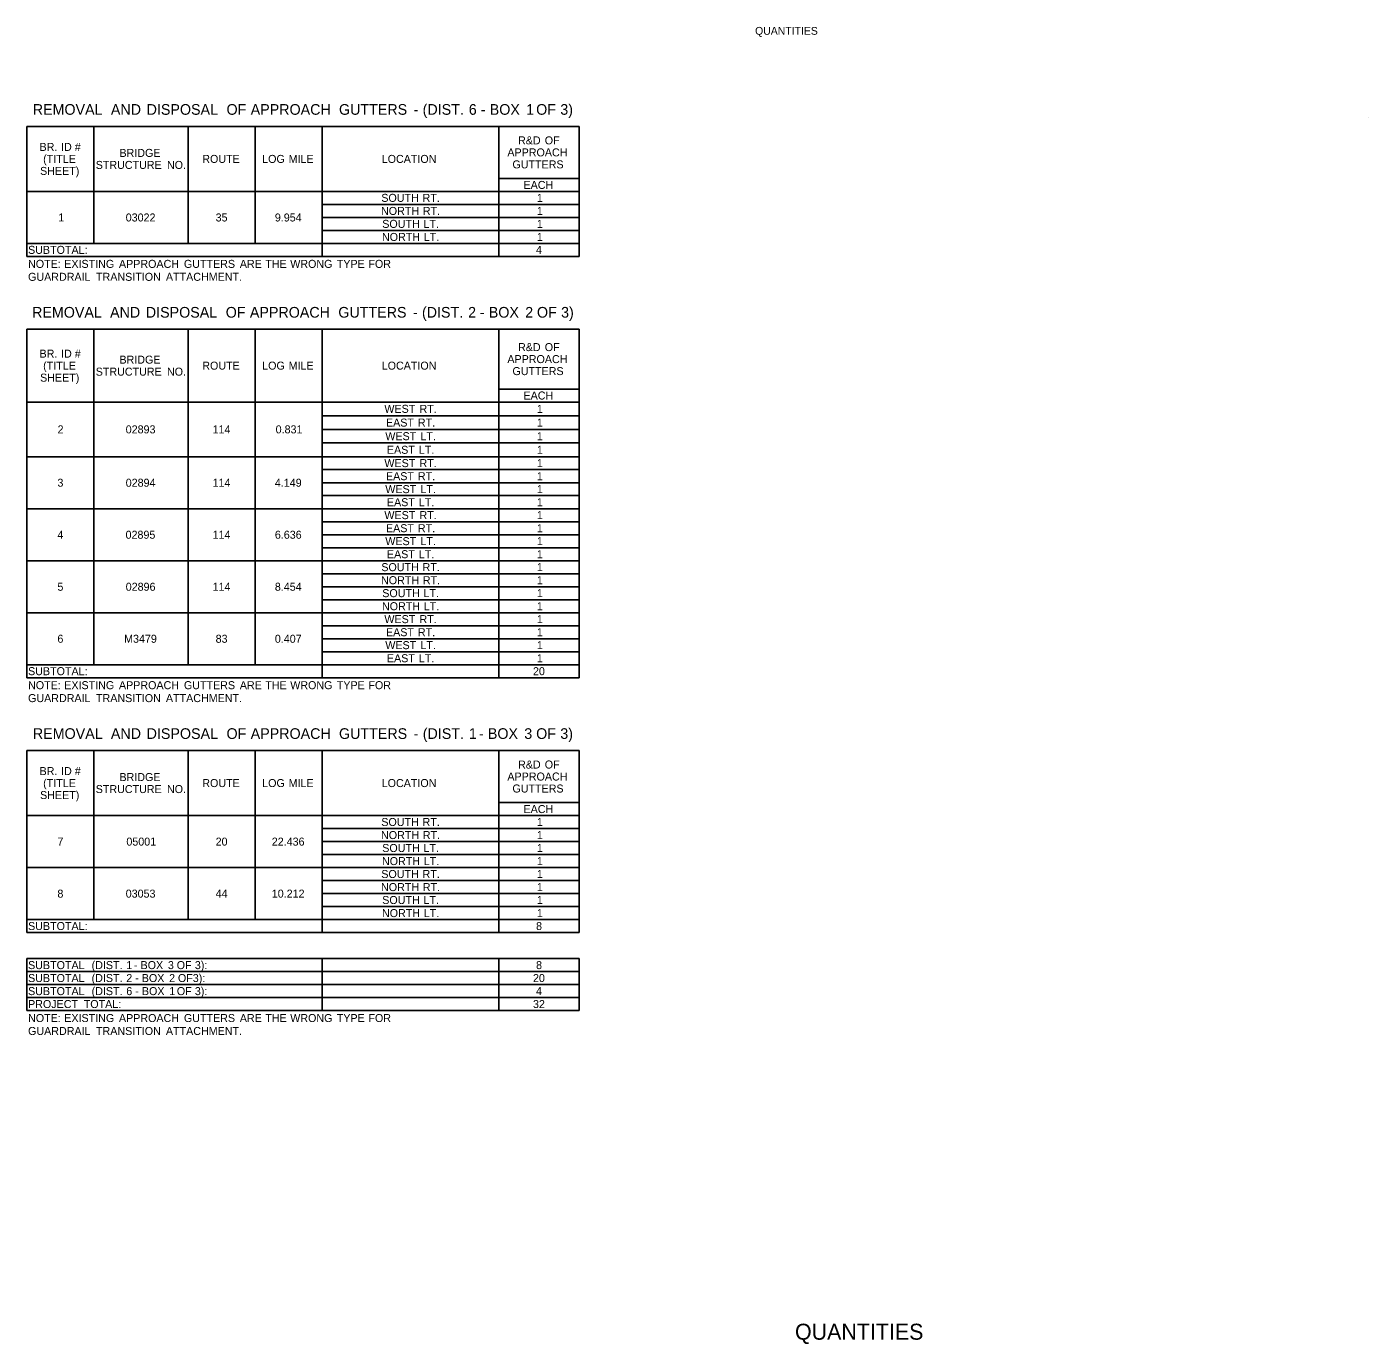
# Model space of a CAD drawing. Extents: x 542596 to 1930787, y -1948294 to 596640.
# Drawn here: x 560317 to 561323, y -1947044 to -1946056 of the extents above; entities that cross this region are included whole.
import ezdxf

# ---------------------------------------------------------------- set-up
doc = ezdxf.new("R2010")
doc.units = 0
for name, color, linetype in [('Default', 7, 'Continuous'), ('R_Border', 7, 'Continuous'), ('R_Border Prem', 7, 'Continuous')]:
    doc.layers.add(name, color=color, linetype=linetype)

msp = doc.modelspace()

# ---------------------------------------------------------------- linework, layer by layer
at = {"layer": 'Default'}
for p, q in [((560317.3, -1946131.1), (560731.2, -1946131.1)), ((560317.3, -1946228.6), (560317.3, -1946131.1)), ((560317.3, -1946228.6), (560317.3, -1946131.1)), ((560367.5, -1946218.9), (560367.5, -1946131.1)), ((560438.2, -1946218.9), (560438.2, -1946131.1)), ((560488.4, -1946218.9), (560488.4, -1946131.1)), ((560538.6, -1946228.6), (560538.6, -1946131.1)), ((560671.2, -1946228.6), (560671.2, -1946131.1)), ((560731.2, -1946228.6), (560731.2, -1946131.1)), ((561322.8, -1946124.4), (561322.8, -1946124.4)), ((560671.2, -1946170.1), (560731.2, -1946170.1)), ((560671.2, -1946170.1), (560731.2, -1946170.1)), ((560317.3, -1946179.9), (560731.2, -1946179.9)), ((560438.2, -1946179.9), (560538.6, -1946179.9)), ((560538.6, -1946189.6), (560731.2, -1946189.6)), ((560538.6, -1946199.4), (560731.2, -1946199.4)), ((560538.6, -1946209.1), (560731.2, -1946209.1)), ((560317.3, -1946218.9), (560731.2, -1946218.9)), ((560538.6, -1946228.6), (560538.6, -1946218.9)), ((560671.2, -1946218.9), (560731.2, -1946218.9)), ((560317.3, -1946228.6), (560731.2, -1946228.6)), ((560317.3, -1946283.2), (560731.2, -1946283.2)), ((560317.3, -1946544.5), (560317.3, -1946283.2)), ((560317.3, -1946544.5), (560317.3, -1946283.2)), ((560367.5, -1946534.8), (560367.5, -1946283.2)), ((560438.2, -1946534.8), (560438.2, -1946283.2)), ((560488.4, -1946534.8), (560488.4, -1946283.2)), ((560538.6, -1946544.5), (560538.6, -1946283.2)), ((560671.2, -1946544.5), (560671.2, -1946283.2)), ((560731.2, -1946544.5), (560731.2, -1946283.2)), ((560671.2, -1946328.1), (560731.2, -1946328.1)), ((560671.2, -1946328.1), (560731.2, -1946328.1)), ((560317.3, -1946337.8), (560731.2, -1946337.8)), ((560671.2, -1946337.8), (560731.2, -1946337.8)), ((560538.6, -1946348.1), (560731.2, -1946348.1)), ((560538.6, -1946358.3), (560731.2, -1946358.3)), ((560538.6, -1946368.5), (560731.2, -1946368.5)), ((560317.3, -1946378.8), (560671.2, -1946378.8)), ((560538.6, -1946378.8), (560671.2, -1946378.8)), ((560671.2, -1946378.8), (560731.2, -1946378.8)), ((560671.2, -1946378.8), (560731.2, -1946378.8)), ((560538.6, -1946388.5), (560731.2, -1946388.5)), ((560538.6, -1946398.3), (560731.2, -1946398.3)), ((560538.6, -1946408), (560731.2, -1946408)), ((560317.3, -1946417.8), (560731.2, -1946417.8)), ((560538.6, -1946417.8), (560671.2, -1946417.8)), ((560671.2, -1946417.8), (560731.2, -1946417.8)), ((560538.6, -1946427.5), (560731.2, -1946427.5)), ((560538.6, -1946437.3), (560731.2, -1946437.3)), ((560538.6, -1946447), (560731.2, -1946447)), ((560317.3, -1946456.8), (560731.2, -1946456.8)), ((560538.6, -1946456.8), (560671.2, -1946456.8)), ((560671.2, -1946456.8), (560731.2, -1946456.8)), ((560538.6, -1946466.5), (560731.2, -1946466.5)), ((560538.6, -1946476.3), (560731.2, -1946476.3)), ((560538.6, -1946486), (560731.2, -1946486)), ((560317.3, -1946495.8), (560731.2, -1946495.8)), ((560317.3, -1946495.8), (560538.6, -1946495.8)), ((560538.6, -1946505.5), (560731.2, -1946505.5)), ((560538.6, -1946515.3), (560731.2, -1946515.3)), ((560538.6, -1946525), (560731.2, -1946525)), ((560317.3, -1946534.8), (560731.2, -1946534.8)), ((560538.6, -1946534.8), (560671.2, -1946534.8)), ((560538.6, -1946544.5), (560538.6, -1946534.8)), ((560671.2, -1946534.8), (560731.2, -1946534.8)), ((560317.3, -1946544.5), (560731.2, -1946544.5)), ((560317.3, -1946599.1), (560731.2, -1946599.1)), ((560317.3, -1946735.6), (560317.3, -1946599.1)), ((560317.3, -1946735.6), (560317.3, -1946599.1)), ((560367.5, -1946725.9), (560367.5, -1946599.1)), ((560438.2, -1946725.9), (560438.2, -1946599.1)), ((560488.4, -1946725.9), (560488.4, -1946599.1)), ((560538.6, -1946735.6), (560538.6, -1946599.1)), ((560671.2, -1946735.6), (560671.2, -1946599.1)), ((560731.2, -1946735.6), (560731.2, -1946599.1)), ((560671.2, -1946638.1), (560731.2, -1946638.1)), ((560671.2, -1946638.1), (560731.2, -1946638.1)), ((560317.3, -1946647.9), (560731.2, -1946647.9)), ((560538.6, -1946657.6), (560731.2, -1946657.6)), ((560538.6, -1946667.4), (560731.2, -1946667.4)), ((560538.6, -1946677.1), (560731.2, -1946677.1)), ((560317.3, -1946686.9), (560731.2, -1946686.9)), ((560438.2, -1946686.9), (560538.6, -1946686.9)), ((560538.6, -1946696.6), (560731.2, -1946696.6)), ((560538.6, -1946706.4), (560731.2, -1946706.4)), ((560538.6, -1946716.1), (560731.2, -1946716.1)), ((560317.3, -1946725.9), (560731.2, -1946725.9)), ((560538.6, -1946735.6), (560538.6, -1946725.9)), ((560317.3, -1946735.6), (560731.2, -1946735.6)), ((560317.3, -1946755.1), (560731.2, -1946755.1)), ((560317.3, -1946755.1), (560731.2, -1946755.1)), ((560317.3, -1946794.1), (560317.3, -1946755.1)), ((560317.3, -1946794.1), (560317.3, -1946755.1)), ((560538.6, -1946784.4), (560538.6, -1946755.1)), ((560538.6, -1946794.1), (560538.6, -1946755.1)), ((560671.2, -1946794.1), (560671.2, -1946755.1)), ((560731.2, -1946794.1), (560731.2, -1946755.1)), ((560317.3, -1946764.9), (560731.2, -1946764.9)), ((560317.3, -1946774.6), (560731.2, -1946774.6)), ((560317.3, -1946784.4), (560731.2, -1946784.4)), ((560317.3, -1946794.1), (560731.2, -1946794.1))]:
    msp.add_line(p, q, dxfattribs=at)

# ---------------------------------------------------------------- texts
for s, height, p in [('REMOVAL', 8, (560321.7, -1946122.4)), (' AND', 8, (560377.3, -1946122.4)), (' DISPOSAL', 8, (560404.1, -1946122.4)), (' OF', 8, (560464, -1946122.4)), (' APPROACH', 8, (560482.1, -1946122.4)), (' GUTTERS', 8, (560548.3, -1946122.4)), (' -', 8, (560604.3, -1946122.4)), (' (DIST.', 8, (560611, -1946122.4)), (' 6', 8, (560645.6, -1946122.4)), (' -', 8, (560654.6, -1946122.4)), (' BOX', 8, (560661.3, -1946122.4)), (' 1', 8, (560688.6, -1946122.4)), (' OF', 8, (560696.1, -1946122.4)), (' 3)', 8, (560714.2, -1946122.4)), ('BR.', 6, (560326.8, -1946149.5)), (' ID', 6, (560340.7, -1946149.5)), (' #', 6, (560351, -1946149.5)), ('R&D', 6, (560685.5, -1946144.6)), (' OF', 6, (560703.3, -1946144.6)), ('(TITLE', 6, (560329.5, -1946158.5)), ('BRIDGE', 6, (560386.7, -1946154)), ('ROUTE', 6, (560448.8, -1946158.5)), ('LOG', 6, (560493.7, -1946158.5)), (' MILE', 6, (560511.3, -1946158.5)), ('LOCATION', 6, (560583.3, -1946158.5)), ('APPROACH', 6, (560677.5, -1946153.6)), ('SHEET)', 6, (560327.2, -1946167.5)), ('STRUCTURE', 6, (560368.9, -1946163)), (' NO.', 6, (560420.1, -1946163)), ('GUTTERS', 6, (560681.3, -1946162.6)), ('EACH', 6, (560689.6, -1946178)), ('SOUTH', 6, (560583, -1946187.7)), (' RT.', 6, (560611.7, -1946187.7)), ('1', 6, (560699.6, -1946187.7)), ('NORTH', 6, (560582.8, -1946197.5)), (' RT.', 6, (560611.9, -1946197.5)), ('1', 6, (560699.6, -1946197.5)), ('1', 6, (560340.8, -1946202.4)), ('03022', 6, (560391.4, -1946202.4)), ('35', 6, (560458.8, -1946202.4)), ('9.954', 6, (560503.2, -1946202.4)), ('SOUTH', 6, (560583.7, -1946207.2)), (' LT.', 6, (560612.4, -1946207.2)), ('1', 6, (560699.6, -1946207.2)), ('NORTH', 6, (560583.5, -1946217)), (' LT.', 6, (560612.6, -1946217)), ('1', 6, (560699.6, -1946217)), ('SUBTOTAL:', 6, (560318.2, -1946226.7)), ('4', 6, (560698.9, -1946226.7)), ('NOTE:', 6, (560318.2, -1946237.2)), (' EXISTING', 6, (560343.1, -1946237.2)), (' APPROACH', 6, (560384.1, -1946237.2)), (' GUTTERS', 6, (560432.8, -1946237.2)), (' ARE', 6, (560474.7, -1946237.2)), (' THE', 6, (560493.8, -1946237.2)), (' WRONG', 6, (560512.5, -1946237.2)), (' TYPE', 6, (560547.4, -1946237.2)), (' FOR', 6, (560571.1, -1946237.2)), ('GUARDRAIL', 6, (560318.2, -1946246.9)), (' TRANSITION', 6, (560366.9, -1946246.9)), (' ATTACHMENT.', 6, (560419.3, -1946246.9)), ('REMOVAL', 8, (560321.2, -1946274.5)), (' AND', 8, (560376.7, -1946274.5)), (' DISPOSAL', 8, (560403.5, -1946274.5)), (' OF', 8, (560463.4, -1946274.5)), (' APPROACH', 8, (560481.5, -1946274.5)), (' GUTTERS', 8, (560547.8, -1946274.5)), (' -', 8, (560603.7, -1946274.5)), (' (DIST.', 8, (560610.5, -1946274.5)), (' 2', 8, (560645.1, -1946274.5)), (' -', 8, (560653.9, -1946274.5)), (' BOX', 8, (560660.6, -1946274.5)), (' 2', 8, (560687.9, -1946274.5)), (' OF', 8, (560696.7, -1946274.5)), (' 3)', 8, (560714.8, -1946274.5)), ('R&D', 6, (560685.5, -1946299.6)), (' OF', 6, (560703.3, -1946299.6)), ('BR.', 6, (560326.8, -1946304.5)), (' ID', 6, (560340.7, -1946304.5)), (' #', 6, (560351, -1946304.5)), ('BRIDGE', 6, (560386.7, -1946309)), ('APPROACH', 6, (560677.5, -1946308.6)), ('(TITLE', 6, (560329.5, -1946313.5)), ('STRUCTURE', 6, (560368.9, -1946318)), (' NO.', 6, (560420.1, -1946318)), ('ROUTE', 6, (560448.8, -1946313.5)), ('LOG', 6, (560493.7, -1946313.5)), (' MILE', 6, (560511.3, -1946313.5)), ('LOCATION', 6, (560583.3, -1946313.5)), ('GUTTERS', 6, (560681.3, -1946317.6)), ('SHEET)', 6, (560327.2, -1946322.5)), ('EACH', 6, (560689.6, -1946335.9)), ('WEST', 6, (560585.3, -1946345.9)), (' RT.', 6, (560609.4, -1946345.9)), ('1', 6, (560699.6, -1946345.9)), ('EAST', 6, (560586.5, -1946356.2)), (' RT.', 6, (560608.2, -1946356.2)), ('1', 6, (560699.6, -1946356.2)), ('2', 6, (560340.3, -1946361.3)), ('02893', 6, (560391.4, -1946361.3)), ('114', 6, (560456.5, -1946361.3)), ('0.831', 6, (560503.8, -1946361.3)), ('WEST', 6, (560586, -1946366.4)), (' LT.', 6, (560610.1, -1946366.4)), ('1', 6, (560699.6, -1946366.4)), ('EAST', 6, (560587.2, -1946376.6)), (' LT.', 6, (560608.9, -1946376.6)), ('1', 6, (560699.6, -1946376.6)), ('WEST', 6, (560585.3, -1946386.6)), (' RT.', 6, (560609.4, -1946386.6)), ('1', 6, (560699.6, -1946386.6)), ('EAST', 6, (560586.5, -1946396.4)), (' RT.', 6, (560608.2, -1946396.4)), ('1', 6, (560699.6, -1946396.4)), ('3', 6, (560340.2, -1946401.3)), ('02894', 6, (560391.4, -1946401.3)), ('114', 6, (560456.5, -1946401.3)), ('4.149', 6, (560503.2, -1946401.3)), ('WEST', 6, (560586, -1946406.1)), (' LT.', 6, (560610.1, -1946406.1)), ('1', 6, (560699.6, -1946406.1)), ('EAST', 6, (560587.2, -1946415.9)), (' LT.', 6, (560608.9, -1946415.9)), ('1', 6, (560699.6, -1946415.9)), ('WEST', 6, (560585.3, -1946425.6)), (' RT.', 6, (560609.4, -1946425.6)), ('1', 6, (560699.6, -1946425.6)), ('4', 6, (560340.2, -1946440.3)), ('02895', 6, (560391.3, -1946440.3)), ('114', 6, (560456.5, -1946440.3)), ('6.636', 6, (560503.2, -1946440.3)), ('EAST', 6, (560586.5, -1946435.4)), (' RT.', 6, (560608.2, -1946435.4)), ('1', 6, (560699.6, -1946435.4)), ('WEST', 6, (560586, -1946445.1)), (' LT.', 6, (560610.1, -1946445.1)), ('1', 6, (560699.6, -1946445.1)), ('EAST', 6, (560587.2, -1946454.9)), (' LT.', 6, (560608.9, -1946454.9)), ('1', 6, (560699.6, -1946454.9)), ('SOUTH', 6, (560583, -1946464.6)), (' RT.', 6, (560611.7, -1946464.6)), ('1', 6, (560699.6, -1946464.6)), ('5', 6, (560340.2, -1946479.3)), ('02896', 6, (560391.4, -1946479.3)), ('114', 6, (560456.5, -1946479.3)), ('8.454', 6, (560503.2, -1946479.3)), ('NORTH', 6, (560582.8, -1946474.4)), (' RT.', 6, (560611.9, -1946474.4)), ('1', 6, (560699.6, -1946474.4)), ('SOUTH', 6, (560583.7, -1946484.1)), (' LT.', 6, (560612.4, -1946484.1)), ('1', 6, (560699.6, -1946484.1)), ('NORTH', 6, (560583.5, -1946493.9)), (' LT.', 6, (560612.6, -1946493.9)), ('1', 6, (560699.6, -1946493.9)), ('WEST', 6, (560585.3, -1946503.6)), (' RT.', 6, (560609.4, -1946503.6)), ('1', 6, (560699.6, -1946503.6)), ('6', 6, (560340.2, -1946518.3)), ('M3479', 6, (560390.2, -1946518.3)), ('83', 6, (560458.8, -1946518.3)), ('0.407', 6, (560503.2, -1946518.3)), ('EAST', 6, (560586.5, -1946513.4)), (' RT.', 6, (560608.2, -1946513.4)), ('1', 6, (560699.6, -1946513.4)), ('WEST', 6, (560586, -1946523.1)), (' LT.', 6, (560610.1, -1946523.1)), ('1', 6, (560699.6, -1946523.1)), ('EAST', 6, (560587.2, -1946532.9)), (' LT.', 6, (560608.9, -1946532.9)), ('1', 6, (560699.6, -1946532.9)), ('SUBTOTAL:', 6, (560318.2, -1946542.6)), ('20', 6, (560696.7, -1946542.6)), ('NOTE:', 6, (560318.2, -1946553.1)), (' EXISTING', 6, (560343.1, -1946553.1)), (' APPROACH', 6, (560384.1, -1946553.1)), (' GUTTERS', 6, (560432.8, -1946553.1)), (' ARE', 6, (560474.7, -1946553.1)), (' THE', 6, (560493.8, -1946553.1)), (' WRONG', 6, (560512.5, -1946553.1)), (' TYPE', 6, (560547.4, -1946553.1)), (' FOR', 6, (560571.1, -1946553.1)), ('GUARDRAIL', 6, (560318.2, -1946562.8)), (' TRANSITION', 6, (560366.9, -1946562.8)), (' ATTACHMENT.', 6, (560419.3, -1946562.8)), ('REMOVAL', 8, (560321.8, -1946590.4)), (' AND', 8, (560377.3, -1946590.4)), (' DISPOSAL', 8, (560404.1, -1946590.4)), (' OF', 8, (560464, -1946590.4)), (' APPROACH', 8, (560482.1, -1946590.4)), (' GUTTERS', 8, (560548.3, -1946590.4)), (' (DIST.', 8, (560611.1, -1946590.4)), (' 1', 8, (560645.7, -1946590.4)), (' BOX', 8, (560659.9, -1946590.4)), (' 3', 8, (560687.2, -1946590.4)), (' OF', 8, (560696.1, -1946590.4)), (' 3)', 8, (560714.2, -1946590.4)), (' -', 8, (560604.3, -1946590.4)), (' -', 8, (560653.2, -1946590.4)), ('BR.', 6, (560326.8, -1946617.5)), (' ID', 6, (560340.7, -1946617.5)), (' #', 6, (560351, -1946617.5)), ('BRIDGE', 6, (560386.7, -1946622)), ('APPROACH', 6, (560677.5, -1946621.6)), ('R&D', 6, (560685.5, -1946612.6)), (' OF', 6, (560703.3, -1946612.6)), ('(TITLE', 6, (560329.5, -1946626.5)), ('STRUCTURE', 6, (560368.9, -1946631)), (' NO.', 6, (560420.1, -1946631)), ('ROUTE', 6, (560448.8, -1946626.5)), ('LOG', 6, (560493.7, -1946626.5)), (' MILE', 6, (560511.3, -1946626.5)), ('LOCATION', 6, (560583.3, -1946626.5)), ('GUTTERS', 6, (560681.3, -1946630.6)), ('SHEET)', 6, (560327.2, -1946635.5)), ('EACH', 6, (560689.6, -1946646)), ('SOUTH', 6, (560583, -1946655.7)), (' RT.', 6, (560611.7, -1946655.7)), ('1', 6, (560699.6, -1946655.7)), ('7', 6, (560340.2, -1946670.4)), ('05001', 6, (560391.9, -1946670.4)), ('20', 6, (560458.8, -1946670.4)), ('22.436', 6, (560500.9, -1946670.4)), ('NORTH', 6, (560582.8, -1946665.5)), (' RT.', 6, (560611.9, -1946665.5)), ('1', 6, (560699.6, -1946665.5)), ('SOUTH', 6, (560583.7, -1946675.2)), (' LT.', 6, (560612.4, -1946675.2)), ('1', 6, (560699.6, -1946675.2)), ('NORTH', 6, (560583.5, -1946685)), (' LT.', 6, (560612.6, -1946685)), ('1', 6, (560699.6, -1946685)), ('SOUTH', 6, (560583, -1946694.7)), (' RT.', 6, (560611.7, -1946694.7)), ('1', 6, (560699.6, -1946694.7)), ('8', 6, (560340.2, -1946709.4)), ('03053', 6, (560391.4, -1946709.4)), ('44', 6, (560458.8, -1946709.4)), ('10.212', 6, (560500.9, -1946709.4)), ('NORTH', 6, (560582.8, -1946704.5)), (' RT.', 6, (560611.9, -1946704.5)), ('1', 6, (560699.6, -1946704.5)), ('SOUTH', 6, (560583.7, -1946714.2)), (' LT.', 6, (560612.4, -1946714.2)), ('1', 6, (560699.6, -1946714.2)), ('NORTH', 6, (560583.5, -1946724)), (' LT.', 6, (560612.6, -1946724)), ('1', 6, (560699.6, -1946724)), ('SUBTOTAL:', 6, (560318.2, -1946733.7)), ('8', 6, (560699, -1946733.7)), ('SUBTOTAL', 6, (560318.2, -1946763)), (' (DIST.', 6, (560363.6, -1946763)), (' 1', 6, (560389.6, -1946763)), (' BOX', 6, (560400.3, -1946763)), (' 3', 6, (560420.8, -1946763)), (' OF', 6, (560427.4, -1946763)), (' 3):', 6, (560441, -1946763)), ('8', 6, (560699, -1946763)), ('SUBTOTAL', 6, (560318.2, -1946772.7)), (' (DIST.', 6, (560363.6, -1946772.7)), (' 2', 6, (560389.6, -1946772.7)), (' -', 6, (560395.2, -1946763)), (' BOX', 6, (560401.2, -1946772.7)), (' 2', 6, (560421.7, -1946772.7)), (' OF3):', 6, (560428.3, -1946772.7)), ('20', 6, (560696.7, -1946772.7)), ('SUBTOTAL', 6, (560318.2, -1946782.5)), (' (DIST.', 6, (560363.6, -1946782.5)), (' 6', 6, (560389.6, -1946782.5)), (' -', 6, (560396.2, -1946772.7)), (' BOX', 6, (560401.3, -1946782.5)), (' 1', 6, (560421.8, -1946782.5)), (' OF', 6, (560427.5, -1946782.5)), (' 3):', 6, (560441, -1946782.5)), ('4', 6, (560698.9, -1946782.5)), ('PROJECT', 6, (560318.2, -1946792.2)), (' TOTAL:', 6, (560357.7, -1946792.2)), (' -', 6, (560396.3, -1946782.5)), ('32', 6, (560696.7, -1946792.2)), ('NOTE:', 6, (560318.2, -1946802.7)), (' EXISTING', 6, (560343.1, -1946802.7)), (' APPROACH', 6, (560384.1, -1946802.7)), (' GUTTERS', 6, (560432.8, -1946802.7)), (' ARE', 6, (560474.7, -1946802.7)), (' THE', 6, (560493.8, -1946802.7)), (' WRONG', 6, (560512.5, -1946802.7)), (' TYPE', 6, (560547.4, -1946802.7)), (' FOR', 6, (560571.1, -1946802.7)), ('GUARDRAIL', 6, (560318.2, -1946812.4)), (' TRANSITION', 6, (560366.9, -1946812.4)), (' ATTACHMENT.', 6, (560419.3, -1946812.4))]:
    msp.add_text(s, height=height, dxfattribs=at).set_placement(p)
at = {"layer": 'R_Border'}
msp.add_text('QUANTITIES', height=12, rotation=360, dxfattribs=at).set_placement((560893.1, -1947040.9))
at = {"layer": 'R_Border Prem'}
msp.add_text('QUANTITIES', height=5.86, rotation=360, dxfattribs=at).set_placement((560863.2, -1946062.4))

doc.saveas('drawing.dxf')
